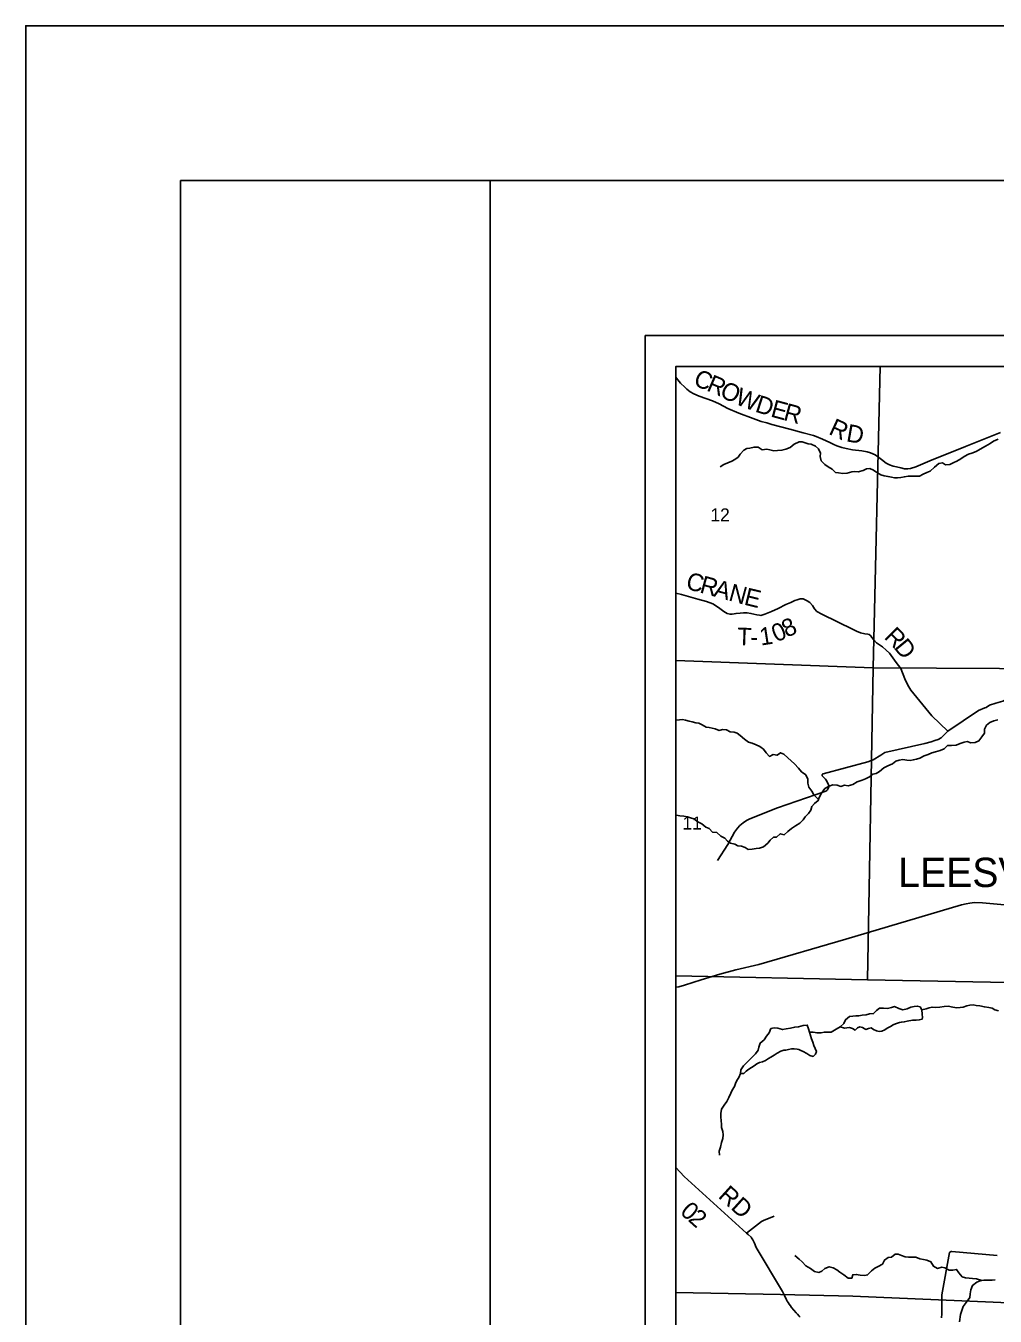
# Model space of a CAD drawing. Extents: x 0 to 34, y 0 to 22.
# Drawn here: x 0 to 3.131, y 17.833 to 22 of the extents above; entities that cross this region are included whole.
import ezdxf

# ---------------------------------------------------------------- set-up
doc = ezdxf.new("R2010")
doc.units = 0
for name, color, linetype in [('Default', 7, 'Continuous'), ('GM_X_Corporation', 7, 'Continuous'), ('GM_X_County_Road_Text', 7, 'Continuous'), ('GM_X_Interchange_Ramps', 7, 'Continuous'), ('GM_X_Interstate_Route', 7, 'Continuous'), ('GM_X_Major_River_Text', 7, 'Continuous'), ('GM_X_Minor_Lake', 7, 'Continuous'), ('GM_X_Minor_River', 7, 'Continuous'), ('GM_X_Section', 7, 'Continuous'), ('GM_X_Township_Road_Text', 7, 'Continuous'), ('SH_Border', 7, 'Continuous'), ('SH_Cut_Line', 7, 'Continuous'), ('SH_Data', 7, 'Continuous')]:
    doc.layers.add(name, color=color, linetype=linetype)

msp = doc.modelspace()

# ---------------------------------------------------------------- linework, layer by layer
at = {"layer": 'Default'}
for points in [[(2.759, 20.9), (2.1, 20.9), (2.1, 19.9499), (2.7373, 19.9264)], [(3.7753, 20.9), (2.759, 20.9), (2.7373, 19.9264), (3.7574, 19.9211), (3.7556, 20.0185)], [(2.1, 19.9499), (2.1, 18.932), (2.719, 18.9194), (2.7373, 19.9264)]]:
    msp.add_lwpolyline(points, close=True, dxfattribs=at)
at = {"layer": 'GM_X_Corporation'}
for points in [[(2.1, 18.8956), (2.109, 18.8968), (2.1275, 18.9017), (2.1814, 18.9185), (2.2418, 18.9368), (2.293, 18.9513), (2.3675, 18.9688), (2.6484, 19.0502), (3.0219, 19.1608), (3.0376, 19.1648), (3.0493, 19.1666), (3.0647, 19.1685), (3.0897, 19.1679), (3.1971, 19.1578), (3.225, 19.1553), (3.244, 19.1548), (3.2547, 19.1546), (3.2795, 19.1586), (3.364, 19.1721), (3.3779, 19.1781), (3.4083, 19.1935), (3.4181, 19.2006), (3.4252, 19.2052), (3.4595, 19.217)], [(2.4442, 17.9125), (2.4503, 17.8998), (2.4572, 17.8857), (2.4595, 17.8815), (2.4624, 17.8765), (2.4658, 17.8714), (2.4699, 17.8657), (2.4734, 17.8613), (2.4884, 17.8437), (2.4928, 17.8388), (2.4979, 17.8332), (2.5013, 17.8296)]]:
    msp.add_lwpolyline(points, dxfattribs=at)
at = {"layer": 'GM_X_Interchange_Ramps'}
msp.add_lwpolyline([(6.6698, 20.9), (2.1, 20.9), (2.1, 17.9098), (2.4376, 17.9025), (2.6711, 17.8975), (2.9484, 17.8857), (3.604, 17.8577), (3.7063, 17.8588), (3.7128, 17.9822), (4.1825, 17.9744), (4.4481, 17.9728), (4.5919, 17.9719), (4.9267, 17.9702), (4.9368, 17.9702), (4.994, 17.969), (5.3871, 17.9608), (5.6339, 17.9555), (6.0729, 17.9463), (6.24, 17.9427), (6.5943, 17.9356), (6.6079, 18.3189), (6.6258, 18.9603), (6.6304, 19.2166), (6.6438, 19.9593)], close=True, dxfattribs=at)
msp.add_lwpolyline([(6.5883, 17.471), (6.5943, 17.9356), (6.24, 17.9427), (6.0729, 17.9463), (5.6339, 17.9555), (5.3871, 17.9608), (4.994, 17.969), (4.9368, 17.9702), (4.9267, 17.9702), (4.5919, 17.9719), (4.4481, 17.9728), (4.1825, 17.9744), (3.7128, 17.9822), (3.7063, 17.8588), (3.604, 17.8577), (2.9484, 17.8857), (2.6711, 17.8975), (2.4376, 17.9025), (2.1, 17.9098), (2.1, 14.1)], dxfattribs=at)
at = {"layer": 'GM_X_Interstate_Route'}
for points in [[(2.1, 20.8653), (2.1018, 20.8623), (2.115, 20.8461), (2.1285, 20.8326), (2.1347, 20.8263), (2.1459, 20.8184), (2.1582, 20.8114), (2.1754, 20.8042), (2.2182, 20.7891), (2.2394, 20.7795), (2.268, 20.7646), (2.3035, 20.7487), (2.3494, 20.732), (2.3748, 20.7226), (2.3939, 20.7174), (2.4099, 20.7124), (2.4678, 20.697), (2.5105, 20.6857), (2.5442, 20.6769), (2.5532, 20.6733), (2.5737, 20.6655), (2.5965, 20.6544), (2.6097, 20.6482), (2.6195, 20.6438), (2.6357, 20.6386), (2.6499, 20.635), (2.6701, 20.6309), (2.7005, 20.627), (2.7173, 20.6237), (2.7278, 20.6209), (2.7358, 20.6181), (2.7439, 20.6144), (2.7549, 20.6062), (2.7639, 20.5994), (2.7788, 20.5881), (2.7897, 20.582), (2.8015, 20.5778), (2.812, 20.5755), (2.826, 20.572), (2.8378, 20.5698), (2.849, 20.569), (2.858, 20.5704), (2.8748, 20.576), (2.92, 20.5952), (3.0356, 20.6412), (3.1485, 20.6871)], [(2.9777, 19.7218), (2.9266, 19.7717), (2.8588, 19.8549), (2.8486, 19.8707), (2.8393, 19.8916), (2.8259, 19.925), (2.8111, 19.9442), (2.7892, 19.9735), (2.7791, 19.9841), (2.7666, 19.9945), (2.7476, 20.0078), (2.739, 20.0167), (2.7328, 20.0248), (2.7291, 20.0297), (2.7242, 20.0339), (2.7193, 20.0356), (2.7099, 20.0368), (2.6964, 20.0396), (2.6836, 20.0445), (2.6722, 20.0502), (2.5707, 20.0996), (2.5553, 20.1084), (2.5478, 20.1168), (2.5412, 20.1281), (2.5319, 20.1375), (2.5242, 20.1431), (2.5148, 20.1477), (2.5103, 20.1491), (2.5057, 20.1496), (2.501, 20.1493), (2.4974, 20.1482), (2.4911, 20.146), (2.4842, 20.1437), (2.4797, 20.1419), (2.471, 20.1381), (2.4552, 20.1308), (2.4302, 20.1184), (2.4089, 20.1082), (2.3973, 20.1043), (2.3873, 20.1004), (2.3778, 20.097), (2.3736, 20.096), (2.3699, 20.0963), (2.3616, 20.0977), (2.3519, 20.0997), (2.3419, 20.1021), (2.3296, 20.1043), (2.3179, 20.1037), (2.3078, 20.1032), (2.294, 20.1024), (2.2815, 20.1002), (2.2748, 20.0998), (2.2651, 20.1022), (2.2543, 20.1083), (2.2373, 20.1213), (2.2188, 20.1338), (2.1988, 20.1407), (2.1704, 20.1482), (2.1181, 20.1631), (2.1, 20.1676)], [(3.3604, 19.9281), (3.3502, 19.9276), (3.3323, 19.9283), (3.3151, 19.9279), (3.3042, 19.9269), (3.297, 19.9243), (3.2891, 19.918), (3.281, 19.913), (3.2718, 19.905), (3.2666, 19.8972), (3.26, 19.8886), (3.2544, 19.8797), (3.242, 19.8652), (3.2396, 19.8613), (3.2368, 19.8584), (3.2313, 19.8544), (3.2081, 19.8424), (3.1556, 19.8186), (3.1329, 19.8121), (3.1129, 19.8056), (3.1016, 19.7988), (3.0978, 19.7973), (3.0767, 19.7884), (2.9777, 19.7218)], [(2.9777, 19.7218), (2.9623, 19.7063), (2.9564, 19.7006), (2.9471, 19.6955), (2.9364, 19.6923), (2.9238, 19.6881), (2.9034, 19.6821), (2.7743, 19.6533), (2.7622, 19.6447), (2.7366, 19.6296), (2.7194, 19.6235), (2.5754, 19.584), (2.5736, 19.5833), (2.573, 19.5828), (2.5724, 19.582), (2.5719, 19.5811), (2.5718, 19.5794), (2.5722, 19.5783), (2.5732, 19.5771), (2.581, 19.5697), (2.5822, 19.5681)], [(2.5822, 19.5681), (2.5834, 19.5666), (2.5848, 19.5642), (2.592, 19.552), (2.5931, 19.5489), (2.594, 19.5452), (2.5934, 19.5412), (2.5915, 19.5364), (2.5893, 19.5327), (2.587, 19.53), (2.5844, 19.5283), (2.428, 19.4746), (2.3387, 19.4385), (2.3278, 19.4334), (2.3168, 19.4259), (2.3068, 19.4172), (2.2987, 19.4086), (2.2892, 19.3962), (2.2673, 19.3562), (2.2343, 19.3045)], [(2.4442, 17.9125), (2.3592, 18.0542), (2.3536, 18.0682), (2.3481, 18.0795), (2.3441, 18.0858), (2.3426, 18.0876), (2.333, 18.0963), (2.328, 18.1008), (2.1263, 18.2843), (2.1, 18.3126)], [(2.328, 18.1008), (2.3759, 18.1382), (2.3824, 18.1419), (2.4169, 18.1556)], [(3.137, 18.0292), (2.9911, 18.042), (2.9891, 18.0417), (2.987, 18.0411), (2.985, 18.0397), (2.9839, 18.0381), (2.9587, 17.9016)], [(2.9576, 17.828), (2.9584, 17.8402), (2.9587, 17.8481), (2.9588, 17.8556), (2.9587, 17.8627), (2.9584, 17.8747), (2.9587, 17.9016)]]:
    msp.add_lwpolyline(points, dxfattribs=at)
at = {"layer": 'GM_X_Minor_Lake'}
msp.add_lwpolyline([(2.7373, 19.9264), (3.7574, 19.9211), (3.7421, 19.0151), (3.7408, 18.8998), (2.719, 18.9194)], close=True, dxfattribs=at)
at = {"layer": 'GM_X_Minor_River'}
for points in [[(2.8945, 18.822), (2.8887, 18.8318), (2.8792, 18.834), (2.8689, 18.8324), (2.8591, 18.8304), (2.8469, 18.8258), (2.8329, 18.8222), (2.82, 18.8263), (2.8062, 18.8327), (2.7964, 18.8299), (2.7831, 18.8268), (2.7706, 18.827), (2.7577, 18.8277), (2.7479, 18.8204), (2.7381, 18.81), (2.7248, 18.8092), (2.7142, 18.8057), (2.7013, 18.8048), (2.691, 18.8032), (2.6804, 18.8027), (2.6709, 18.8019), (2.6607, 18.8003), (2.6478, 18.7903), (2.6419, 18.7785), (2.6302, 18.767)], [(2.6302, 18.767), (2.6439, 18.7625), (2.6522, 18.7638), (2.661, 18.765), (2.6701, 18.762), (2.6793, 18.7568), (2.6864, 18.7644), (2.694, 18.7668), (2.7028, 18.7649), (2.7134, 18.759), (2.7218, 18.7621), (2.7301, 18.764), (2.7385, 18.7584), (2.7473, 18.7543), (2.756, 18.7525), (2.7644, 18.7537), (2.7742, 18.7572), (2.7825, 18.7626), (2.7924, 18.7688), (2.8014, 18.7734), (2.8094, 18.7765), (2.8219, 18.7815), (2.8279, 18.7827), (2.8374, 18.7832), (2.8469, 18.7855), (2.8636, 18.7887), (2.8754, 18.7888), (2.8856, 18.7897), (2.8947, 18.7917), (2.8966, 18.7974), (2.895, 18.808), (2.8945, 18.822)], [(2.5316, 18.7502), (2.5285, 18.7604), (2.5238, 18.7729), (2.5105, 18.772), (2.4957, 18.7673), (2.4836, 18.7665), (2.4699, 18.7629), (2.4555, 18.7605), (2.4441, 18.7585), (2.4289, 18.7626), (2.4171, 18.764), (2.4069, 18.7616), (2.4013, 18.7483), (2.3919, 18.7376), (2.3844, 18.7254), (2.372, 18.715), (2.3671, 18.7013), (2.3657, 18.6914), (2.3567, 18.6803), (2.3435, 18.6666), (2.3307, 18.6539), (2.3179, 18.6417), (2.3096, 18.6287), (2.3086, 18.6169)], [(2.3086, 18.6169), (2.3189, 18.617), (2.3264, 18.6239), (2.3355, 18.6304), (2.3442, 18.6354), (2.3525, 18.6412), (2.3615, 18.6477), (2.3698, 18.6516), (2.3793, 18.6547), (2.3888, 18.659), (2.3986, 18.6655), (2.4069, 18.6698), (2.4167, 18.6755), (2.4266, 18.6825), (2.439, 18.6883), (2.4489, 18.6914), (2.4546, 18.6922), (2.4637, 18.6945), (2.4735, 18.6958), (2.4819, 18.6962), (2.491, 18.6948), (2.4967, 18.6937), (2.5028, 18.6911), (2.5112, 18.6874), (2.5223, 18.681), (2.5326, 18.6743), (2.5429, 18.6717), (2.5504, 18.6794), (2.5534, 18.6881), (2.5495, 18.6976), (2.5456, 18.7066), (2.5417, 18.7172), (2.5378, 18.7286), (2.5316, 18.7502)]]:
    msp.add_lwpolyline(points, dxfattribs=at)
at = {"layer": 'GM_X_Township_Road_Text'}
for points in [[(2.3388, 20.6358), (2.3294, 20.635), (2.3195, 20.63), (2.3075, 20.617), (2.3007, 20.6071), (2.2906, 20.599), (2.2807, 20.594), (2.2679, 20.5882), (2.255, 20.5835), (2.2425, 20.5762)], [(3.1404, 20.6652), (3.1253, 20.6582), (3.1143, 20.6509), (3.1, 20.6428), (3.083, 20.6332), (3.0701, 20.6255), (3.0557, 20.6197), (3.0447, 20.6169), (3.0311, 20.6096), (3.0198, 20.6019), (3.0073, 20.5938), (2.9975, 20.5896), (2.9843, 20.583), (2.9706, 20.5825), (2.9611, 20.5885), (2.9493, 20.5865), (2.935, 20.5746), (2.9206, 20.562), (2.9101, 20.5573), (2.8987, 20.5516), (2.8866, 20.5461), (2.8722, 20.5453), (2.8627, 20.5459), (2.8501, 20.5451), (2.8376, 20.5438), (2.8263, 20.5414), (2.8152, 20.5402), (2.8058, 20.5405), (2.7962, 20.5419), (2.7852, 20.5441), (2.7723, 20.547), (2.762, 20.55), (2.7486, 20.5575), (2.7375, 20.5653), (2.7257, 20.5705), (2.7155, 20.5697), (2.7049, 20.5643), (2.689, 20.5596), (2.6776, 20.5603), (2.6677, 20.5594), (2.6525, 20.5555), (2.6393, 20.5546), (2.6252, 20.556), (2.6157, 20.5574), (2.6049, 20.5687), (2.5916, 20.5762), (2.5805, 20.5833), (2.5694, 20.5946), (2.5662, 20.6094), (2.5673, 20.6204), (2.5603, 20.634), (2.5504, 20.6426), (2.537, 20.6493), (2.5275, 20.65), (2.5077, 20.6567), (2.4974, 20.6569), (2.4819, 20.6492), (2.4691, 20.6377), (2.4551, 20.6323), (2.4422, 20.6291), (2.4278, 20.6283), (2.4156, 20.6278), (2.4031, 20.6311), (2.3936, 20.6325), (2.3788, 20.6301), (2.365, 20.6391), (2.3521, 20.6394), (2.3388, 20.6358)], [(2.5602, 19.5014), (2.5455, 19.5166), (2.5389, 19.5279), (2.5293, 19.5411), (2.5254, 19.554), (2.526, 19.5672), (2.5199, 19.5808), (2.5057, 19.591), (2.4954, 19.603), (2.4823, 19.6162), (2.4724, 19.6267), (2.4613, 19.6365), (2.4479, 19.6481), (2.4379, 19.6526), (2.4266, 19.6445), (2.4137, 19.6471), (2.402, 19.6405), (2.3912, 19.6522), (2.3831, 19.6635), (2.3709, 19.6729), (2.3595, 19.6781), (2.3461, 19.6829), (2.3343, 19.6862), (2.3217, 19.6967), (2.3072, 19.7084), (2.2972, 19.7155), (2.2877, 19.7188), (2.2755, 19.7202), (2.2629, 19.7266), (2.2504, 19.7276), (2.2398, 19.7245), (2.2268, 19.7297), (2.2169, 19.7323), (2.207, 19.7344), (2.1975, 19.7351), (2.1846, 19.7426), (2.1739, 19.7478), (2.164, 19.7489), (2.1522, 19.7518), (2.1423, 19.754), (2.1313, 19.7581), (2.1214, 19.7595), (2.1119, 19.7583), (2.1, 19.7572)], [(3.1401, 19.7592), (3.1264, 19.7553), (3.1135, 19.7506), (3.103, 19.7411), (3.0967, 19.7281), (3.0964, 19.716), (3.0874, 19.7041), (3.0784, 19.6904), (3.0659, 19.685), (3.0522, 19.6845), (3.0404, 19.6885), (3.0309, 19.6869), (3.0181, 19.6823), (3.0052, 19.6772), (2.9904, 19.6756), (2.9771, 19.6755), (2.9658, 19.6651), (2.9533, 19.6597), (2.9385, 19.6558), (2.9268, 19.6519), (2.9151, 19.6469), (2.9018, 19.6422), (2.8878, 19.6345), (2.8768, 19.6321), (2.8666, 19.629), (2.8563, 19.6278), (2.8457, 19.6281), (2.8324, 19.6302), (2.8214, 19.6286), (2.81, 19.6247), (2.7991, 19.6166), (2.784, 19.6104), (2.7715, 19.6035), (2.7579, 19.5913), (2.7462, 19.5858), (2.7363, 19.5827), (2.7246, 19.575), (2.7118, 19.5677)], [(2.7118, 19.5677), (2.7019, 19.5642), (2.6857, 19.5584), (2.6717, 19.5495), (2.6565, 19.5452), (2.6443, 19.5474), (2.6322, 19.5439), (2.6208, 19.5472), (2.6071, 19.5493), (2.5946, 19.5443), (2.581, 19.5366), (2.5705, 19.5221), (2.5627, 19.508), (2.5589, 19.4981), (2.5473, 19.4885), (2.539, 19.4789), (2.5357, 19.4672), (2.5285, 19.4557), (2.5169, 19.4457), (2.5109, 19.4354), (2.4999, 19.4251), (2.4863, 19.4163), (2.4731, 19.4074), (2.4614, 19.3982), (2.4494, 19.3875), (2.4368, 19.3908), (2.4244, 19.3797), (2.4145, 19.3796), (2.4039, 19.37), (2.3964, 19.3601), (2.3829, 19.3486), (2.3696, 19.3439), (2.359, 19.3427), (2.3465, 19.341), (2.3328, 19.3398), (2.3233, 19.3465), (2.3118, 19.3502), (2.2997, 19.352), (2.2897, 19.3573), (2.2764, 19.3602), (2.2669, 19.3665), (2.2577, 19.3767), (2.2451, 19.3831), (2.2324, 19.3943), (2.2184, 19.3957), (2.2069, 19.4074), (2.1962, 19.4122), (2.1836, 19.4227), (2.1702, 19.4298), (2.1576, 19.4385), (2.1469, 19.4422), (2.1374, 19.4455), (2.1252, 19.4473), (2.1123, 19.4491), (2.102, 19.4505), (2.1, 19.451)], [(3.1417, 18.8184), (3.1303, 18.8225), (3.1208, 18.8274), (3.1109, 18.8296), (3.0964, 18.8317), (3.0812, 18.8346), (3.0694, 18.8364), (3.0595, 18.8386), (3.0489, 18.837), (3.0391, 18.8347), (3.0273, 18.8311), (3.0178, 18.8292), (3.0076, 18.8283), (2.9939, 18.8312), (2.9791, 18.8341), (2.9658, 18.8333), (2.9525, 18.8312), (2.9396, 18.83), (2.9274, 18.831), (2.9176, 18.8287), (2.9077, 18.8255), (2.8945, 18.822), (2.8887, 18.8318), (2.8792, 18.834), (2.8689, 18.8324), (2.8591, 18.8304), (2.8469, 18.8258), (2.8329, 18.8222), (2.82, 18.8263), (2.8062, 18.8327), (2.7964, 18.8299), (2.7831, 18.8268), (2.7706, 18.827), (2.7577, 18.8277), (2.7479, 18.8204), (2.7381, 18.81), (2.7248, 18.8092), (2.7142, 18.8057), (2.7013, 18.8048), (2.691, 18.8032), (2.6804, 18.8027), (2.6709, 18.8019), (2.6607, 18.8003), (2.6478, 18.7903), (2.6419, 18.7785), (2.6302, 18.767), (2.6173, 18.7593), (2.6018, 18.7504), (2.5787, 18.7502), (2.5692, 18.7479), (2.5559, 18.7477), (2.543, 18.7503), (2.5316, 18.7502), (2.5285, 18.7604), (2.5238, 18.7729), (2.5105, 18.772), (2.4957, 18.7673), (2.4836, 18.7665), (2.4699, 18.7629), (2.4555, 18.7605), (2.4441, 18.7585), (2.4289, 18.7626), (2.4171, 18.764), (2.4069, 18.7616), (2.4013, 18.7483), (2.3919, 18.7376), (2.3844, 18.7254), (2.372, 18.715), (2.3671, 18.7013), (2.3657, 18.6914), (2.3567, 18.6803), (2.3435, 18.6666), (2.3307, 18.6539), (2.3179, 18.6417), (2.3096, 18.6287), (2.3086, 18.6169), (2.3026, 18.6039), (2.297, 18.5944), (2.2925, 18.5841), (2.2885, 18.5746), (2.2817, 18.5631), (2.2776, 18.5528), (2.2705, 18.5395), (2.2642, 18.5262), (2.2559, 18.5147), (2.2469, 18.5009), (2.2447, 18.4869), (2.2448, 18.477), (2.2465, 18.4641), (2.2473, 18.4531), (2.2474, 18.4421), (2.2509, 18.4288), (2.2529, 18.419), (2.2515, 18.4061), (2.247, 18.3935), (2.2441, 18.3783)], [(2.2441, 18.3783), (2.2393, 18.3653), (2.2405, 18.3532)], [(3.0884, 17.9482), (3.0708, 17.9534), (3.0582, 17.9544), (3.0472, 17.9554), (3.035, 17.9568), (3.0248, 17.9598), (3.0136, 17.973), (3.0063, 17.9839), (2.9938, 17.9815), (2.982, 17.9811), (2.9683, 17.9889), (2.9584, 17.9915), (2.9448, 17.9872), (2.9314, 17.9943), (2.9233, 18.0079), (2.9107, 18.0135), (2.8993, 18.0164), (2.8879, 18.0182), (2.8742, 18.0234), (2.851, 18.0232), (2.8408, 18.0246), (2.8282, 18.0283), (2.8179, 18.0328), (2.8084, 18.0331), (2.796, 18.0235), (2.7857, 18.0226), (2.7736, 18.0138), (2.7669, 18.0008), (2.7529, 17.9931), (2.7423, 17.9877), (2.731, 17.9789), (2.7189, 17.9659), (2.7095, 17.9639), (2.6954, 17.9653), (2.6825, 17.9678), (2.6711, 17.9666), (2.6685, 17.9559), (2.6567, 17.9551), (2.6426, 17.966), (2.6292, 17.9753), (2.6193, 17.9825), (2.6075, 17.9892), (2.5953, 17.9925), (2.5813, 17.9871), (2.5707, 17.9779), (2.5609, 17.974), (2.5472, 17.9769), (2.5342, 17.9867), (2.5197, 17.9949), (2.5078, 18.0085), (2.4975, 18.0167), (2.4837, 18.0291)], [(3.1312, 17.9501), (3.1213, 17.9496), (3.1065, 17.9491), (3.094, 17.949), (3.0826, 17.9474), (3.0716, 17.9424), (3.0573, 17.932), (3.0521, 17.9179), (3.0507, 17.905), (3.0489, 17.8932), (3.0408, 17.8816)], [(3.0408, 17.8816), (3.0275, 17.8641), (3.0191, 17.8379), (3.0159, 17.8141)]]:
    msp.add_lwpolyline(points, dxfattribs=at)
at = {"layer": 'SH_Border'}
for points in [[(0.5, 21.5), (1.5, 21.5), (1.5, 0.5), (0.5, 0.5)], [(1.5, 21.5), (33.5, 21.5), (33.5, 0.5), (1.5, 0.5)]]:
    msp.add_lwpolyline(points, close=True, dxfattribs=at)
at = {"layer": 'SH_Cut_Line'}
for points in [[(0, 0), (34, 0), (34, 22), (0, 22)], [(8.9, 17.8921), (8.9, 20.9), (2.1, 20.9), (2.1, 17.9098), (2.4376, 17.9025), (2.6711, 17.8975), (2.9484, 17.8857), (3.604, 17.8577), (3.7063, 17.8588), (3.7128, 17.9822), (4.1825, 17.9744), (4.4481, 17.9728), (4.5919, 17.9719), (4.9267, 17.9702), (4.9368, 17.9702), (4.994, 17.969), (5.3871, 17.9608), (5.6339, 17.9555), (6.0729, 17.9463), (6.24, 17.9427), (6.5943, 17.9356), (7.6027, 17.9156), (8.3297, 17.9059), (8.5492, 17.9006)], [(2.1, 17.9098), (2.1, 14.1), (8.9, 14.1), (8.9, 17.8921), (8.5492, 17.9006), (8.3297, 17.9059), (7.6027, 17.9156), (6.5943, 17.9356), (6.24, 17.9427), (6.0729, 17.9463), (5.6339, 17.9555), (5.3871, 17.9608), (4.994, 17.969), (4.9368, 17.9702), (4.9267, 17.9702), (4.5919, 17.9719), (4.4481, 17.9728), (4.1825, 17.9744), (3.7128, 17.9822), (3.7063, 17.8588), (3.604, 17.8577), (2.9484, 17.8857), (2.6711, 17.8975), (2.4376, 17.9025)]]:
    msp.add_lwpolyline(points, close=True, dxfattribs=at)
at = {"layer": 'SH_Data'}
for p, q in [((2, 21), (9, 21)), ((2, 21), (2, 14)), ((2.1, 20.9), (2.1, 14.1)), ((2.1, 20.9), (8.9, 20.9))]:
    msp.add_line(p, q, dxfattribs=at)

# ---------------------------------------------------------------- texts
at = {"layer": 'GM_X_County_Road_Text'}
for s, p in [('12', (2.2115, 20.3998)), ('11', (2.1211, 19.4045))]:
    msp.add_text(s, height=0.04186, rotation=0, dxfattribs=at).set_placement(p)
at = {"layer": 'GM_X_Major_River_Text'}
msp.add_text('LEESVILLE', height=0.0947, rotation=0, dxfattribs=at).set_placement((2.8177, 19.2187))
at = {"layer": 'GM_X_Section'}
for s, height, rotation, p in [('C', 0.0568, 337.4108, (2.153, 20.8409)), ('R', 0.0568, 336.6474, (2.1959, 20.8231)), ('O', 0.0568, 333.2191, (2.2379, 20.805)), ('W', 0.0568, 338.5253, (2.2878, 20.7801)), ('D', 0.0568, 342.2379, (2.3528, 20.7546)), ('E', 0.0568, 344.8007, (2.4031, 20.7386)), ('R', 0.0568, 345.0105, (2.4443, 20.7274)), ('R', 0.0568, 335.172, (2.5902, 20.6827)), ('D', 0.0568, 350.0658, (2.6477, 20.6584)), ('C', 0.0568, 345.0081, (2.1289, 20.1825)), ('R', 0.0568, 344.5953, (2.1739, 20.1705)), ('A', 0.0568, 344.5938, (2.2189, 20.1581)), ('N', 0.0568, 344.6417, (2.2671, 20.1448)), ('E', 0.0568, 346.3372, (2.3171, 20.1311)), ('8', 0.0568, 25.5761, (2.4581, 20.0231)), ('T', 0.0568, 357.9639, (2.2967, 20.0001)), ('1', 0.0568, 8.7869, (2.3742, 19.9984)), ('0', 0.0568, 23.5354, (2.424, 20.0082)), ('R', 0.0568, 314.5915, (2.7698, 20.024)), ('-', 0.0568, 358.0748, (2.3393, 19.9985)), ('D', 0.0568, 309.2774, (2.8016, 19.9918)), ('RD', 0.05682, 317.7918, (2.2336, 18.2177)), ('0', 0.0568, 317.9517, (2.1104, 18.166)), ('2', 0.0568, 318.0315, (2.1364, 18.1425))]:
    msp.add_text(s, height=height, rotation=rotation, dxfattribs=at).set_placement(p)

doc.saveas('drawing.dxf')
